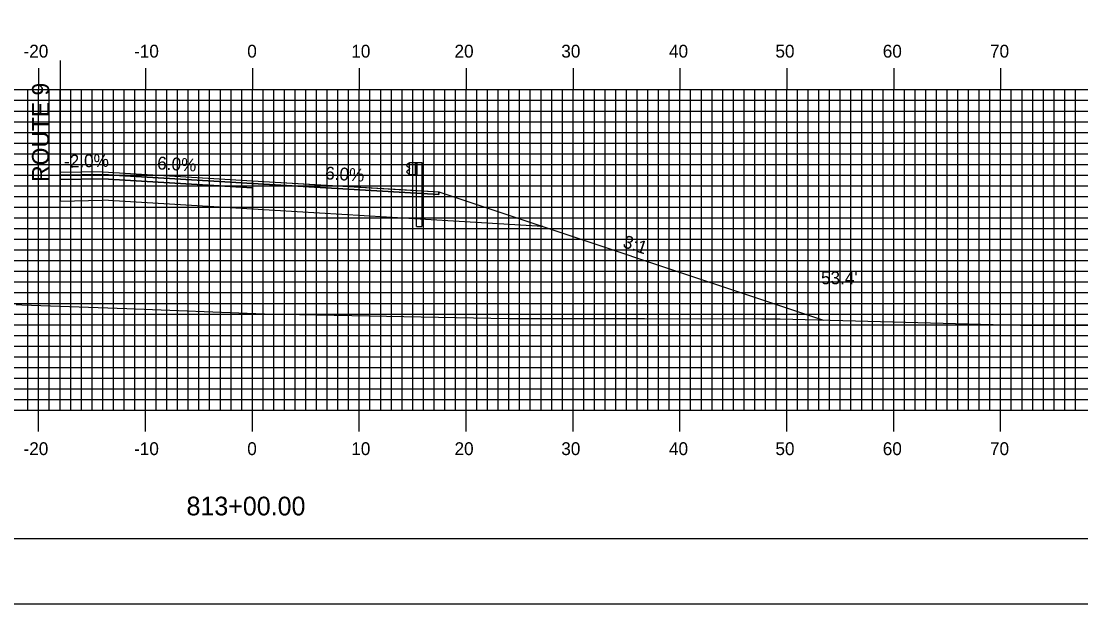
# Model space of a CAD drawing. Extents: x 2453 to 2796, y -1658 to -1438.
# Drawn here: x 2597.1 to 2696.2, y -1657.7 to -1603.2 of the extents above; entities that cross this region are included whole.
import ezdxf

# ---------------------------------------------------------------- set-up
doc = ezdxf.new("R2010")
doc.units = 0
for name, color, linetype in [('ANNOTATION', 7, 'Continuous'), ('BORDER', 7, 'Continuous'), ('D_Guardrail_Beam_Rt', 7, 'Continuous'), ('D_Roadway_Edge_Shoulder', 7, 'Continuous'), ('D_Roadway_Edge_TW', 7, 'Continuous'), ('D_Roadway_Pavement', 7, 'Continuous'), ('D_Roadway_SlopeLines', 7, 'Continuous'), ('D_Roadway_SubGrade', 7, 'Continuous'), ('D_Text_Standard', 7, 'Continuous'), ('H_V ANNOTATION', 7, 'Continuous'), ('MAJOR', 7, 'Continuous'), ('MINOR', 7, 'Continuous'), ('PLOT BOUNDARY', 7, 'Continuous'), ('S_Roadway_Centerline', 7, 'Continuous')]:
    doc.layers.add(name, color=color, linetype=linetype)

msp = doc.modelspace()

# ---------------------------------------------------------------- linework, layer by layer
at = {"layer": 'BORDER'}
msp.add_lwpolyline([(2469.1, -1651.604), (2789.1, -1651.604), (2789.1, -1441.604), (2469.1, -1441.604)], close=True, dxfattribs=at)
at = {"layer": 'D_Guardrail_Beam_Rt'}
for p, q in [((2633.307, -1616.511), (2633.164, -1616.611)), ((2633.164, -1616.754), (2633.359, -1616.891)), ((2633.397, -1616.49), (2633.323, -1616.505)), ((2633.397, -1616.407), (2634.085, -1616.407)), ((2633.397, -1617.573), (2633.397, -1616.407)), ((2633.918, -1616.407), (2633.918, -1617.573)), ((2634.022, -1616.407), (2634.022, -1617.573)), ((2634.085, -1616.407), (2634.555, -1616.407)), ((2634.085, -1616.407), (2634.085, -1617.573)), ((2634.555, -1616.407), (2634.555, -1622.407)), ((2633.359, -1617.089), (2633.164, -1617.226)), ((2633.164, -1617.369), (2633.307, -1617.469)), ((2633.323, -1617.475), (2633.397, -1617.49)), ((2633.393, -1616.955), (2633.393, -1617.025)), ((2634.085, -1617.573), (2633.397, -1617.573)), ((2634.064, -1622.407), (2634.064, -1617.573)), ((2634.064, -1622.407), (2634.555, -1622.407))]:
    msp.add_line(p, q, dxfattribs=at)
for centre, major_axis, start_param, end_param in [((2633.214, -1616.683), (-0.0877, 0), 5.323254, 7.243116), ((2633.331, -1616.545), (-0.0417, 0), 4.907132, 5.323254), ((2633.214, -1617.297), (-0.0877, 0), 5.323254, 7.243116), ((2633.331, -1617.435), (-0.0417, 0), 0.959931, 1.376053), ((2633.314, -1616.955), (0.0789, 0), 0, 0.959931), ((2633.314, -1617.025), (0.0789, 0), 5.323254, 6.283185)]:
    msp.add_ellipse(centre, major_axis=major_axis, ratio=0.995501, start_param=start_param, end_param=end_param, dxfattribs=at)
at = {"layer": 'D_Roadway_Edge_Shoulder'}
for points in [[(2604.7, -1617.284), (2600.7, -1617.361), (2600.7, -1617.611), (2604.7, -1617.534)], [(2604.7, -1617.284), (2600.7, -1617.361), (2600.7, -1617.611), (2604.7, -1617.534)], [(2618.7, -1618.124), (2633.126, -1618.99), (2633.126, -1618.99), (2636.126, -1619.17), (2636.126, -1619.42), (2618.7, -1618.374)], [(2618.7, -1618.124), (2636.126, -1619.17), (2636.126, -1619.42), (2618.7, -1618.374)], [(2618.7, -1618.124), (2633.126, -1618.99), (2633.126, -1618.99), (2636.126, -1619.17), (2636.126, -1619.42), (2618.7, -1618.374)]]:
    msp.add_lwpolyline(points, close=True, dxfattribs=at)
at = {"layer": 'D_Roadway_Edge_TW'}
msp.add_lwpolyline([(2604.7, -1617.284), (2618.7, -1618.124), (2618.7, -1618.374), (2604.7, -1617.534)], close=True, dxfattribs=at)
msp.add_lwpolyline([(2604.7, -1617.284), (2618.7, -1618.124), (2618.7, -1618.374), (2604.7, -1617.534)], close=True, dxfattribs=at)
msp.add_lwpolyline([(2604.7, -1617.284), (2618.7, -1618.124), (2618.7, -1618.374), (2604.7, -1617.534)], close=True, dxfattribs=at)
msp.add_lwpolyline([(2604.7, -1617.284), (2618.7, -1618.124), (2618.7, -1618.374), (2604.7, -1617.534)], close=True, dxfattribs=at)
at = {"layer": 'D_Roadway_Pavement'}
for points in [[(2604.7, -1617.534), (2600.7, -1617.611), (2600.7, -1618.028), (2604.7, -1617.951)], [(2604.7, -1617.534), (2600.7, -1617.611), (2600.7, -1618.028), (2604.7, -1617.951)], [(2604.7, -1617.534), (2618.7, -1618.374), (2618.7, -1618.791), (2604.7, -1617.951)], [(2604.7, -1617.534), (2618.7, -1618.374), (2618.7, -1618.791), (2604.7, -1617.951)], [(2604.7, -1617.534), (2618.7, -1618.374), (2618.7, -1618.791), (2604.7, -1617.951)], [(2604.7, -1617.534), (2618.7, -1618.374), (2618.7, -1618.791), (2604.7, -1617.951)]]:
    msp.add_lwpolyline(points, close=True, dxfattribs=at)
msp.add_lwpolyline([(2618.7, -1618.374), (2618.7, -1618.791)], dxfattribs=at)
msp.add_lwpolyline([(2618.7, -1618.374), (2618.7, -1618.791)], dxfattribs=at)
msp.add_lwpolyline([(2618.7, -1618.374), (2618.7, -1618.791)], dxfattribs=at)
msp.add_lwpolyline([(2618.7, -1618.374), (2618.7, -1618.791)], dxfattribs=at)
msp.add_lwpolyline([(2618.7, -1618.374), (2618.7, -1618.791)], dxfattribs=at)
msp.add_lwpolyline([(2618.7, -1618.374), (2618.7, -1618.791)], dxfattribs=at)
msp.add_lwpolyline([(2618.7, -1618.374), (2618.7, -1618.791)], dxfattribs=at)
msp.add_lwpolyline([(2618.7, -1618.374), (2618.7, -1618.791)], dxfattribs=at)
msp.add_lwpolyline([(2618.7, -1618.374), (2618.7, -1618.791)], dxfattribs=at)
msp.add_lwpolyline([(2618.7, -1618.374), (2618.7, -1618.791)], dxfattribs=at)
msp.add_lwpolyline([(2618.7, -1618.374), (2618.7, -1618.791)], dxfattribs=at)
msp.add_lwpolyline([(2618.7, -1618.374), (2618.7, -1618.791)], dxfattribs=at)
msp.add_lwpolyline([(2618.7, -1618.374), (2618.7, -1618.791)], dxfattribs=at)
msp.add_lwpolyline([(2618.7, -1618.374), (2618.7, -1618.791)], dxfattribs=at)
at = {"layer": 'D_Roadway_SlopeLines'}
msp.add_lwpolyline([(2636.126, -1619.17), (2672.138, -1631.174)], dxfattribs=at)
msp.add_lwpolyline([(2636.126, -1619.17), (2672.138, -1631.174)], dxfattribs=at)
at = {"layer": 'D_Roadway_SubGrade'}
msp.add_line((2600.7, -1606.888), (2600.7, -1620.028), dxfattribs=at)
for points in [[(2604.7, -1617.951), (2600.7, -1618.028), (2600.7, -1617.611), (2600.7, -1620.028), (2604.7, -1619.951)], [(2604.7, -1617.951), (2618.7, -1618.791), (2618.7, -1620.791), (2604.7, -1619.951)], [(2604.7, -1617.951), (2618.7, -1618.791), (2618.7, -1620.791), (2604.7, -1619.951)], [(2604.7, -1617.951), (2618.7, -1618.791), (2618.7, -1620.791), (2604.7, -1619.951)], [(2604.7, -1617.951), (2618.7, -1618.791), (2618.7, -1620.791), (2604.7, -1619.951)], [(2618.7, -1618.791), (2618.7, -1618.374), (2636.126, -1619.42), (2636.126, -1619.17), (2645.882, -1622.422), (2618.7, -1620.791)]]:
    msp.add_lwpolyline(points, close=True, dxfattribs=at)
at = {"layer": 'MAJOR'}
for p, q in [((2598.7, -1607.6), (2598.7, -1609.604)), ((2608.7, -1607.6), (2608.7, -1609.604)), ((2618.7, -1607.6), (2618.7, -1609.604)), ((2628.7, -1607.6), (2628.7, -1609.604)), ((2638.7, -1607.6), (2638.7, -1609.604)), ((2648.7, -1607.6), (2648.7, -1609.604)), ((2658.7, -1607.6), (2658.7, -1609.604)), ((2668.7, -1607.6), (2668.7, -1609.604)), ((2678.7, -1607.6), (2678.7, -1609.604)), ((2688.7, -1607.6), (2688.7, -1609.604)), ((2478.7, -1609.604), (2758.7, -1609.604)), ((2478.7, -1609.604), (2758.7, -1609.604)), ((2598.7, -1639.604), (2598.7, -1609.604)), ((2608.7, -1639.604), (2608.7, -1609.604)), ((2618.7, -1639.604), (2618.7, -1609.604)), ((2628.7, -1639.604), (2628.7, -1609.604)), ((2638.7, -1639.604), (2638.7, -1609.604)), ((2648.7, -1639.604), (2648.7, -1609.604)), ((2658.7, -1639.604), (2658.7, -1609.604)), ((2668.7, -1639.604), (2668.7, -1609.604)), ((2678.7, -1639.604), (2678.7, -1609.604)), ((2688.7, -1639.604), (2688.7, -1609.604)), ((2478.7, -1614.604), (2758.7, -1614.604)), ((2478.7, -1619.604), (2758.7, -1619.604)), ((2478.7, -1624.604), (2758.7, -1624.604)), ((2478.7, -1629.604), (2758.7, -1629.604)), ((2478.7, -1634.604), (2758.7, -1634.604)), ((2478.7, -1639.604), (2758.7, -1639.604)), ((2478.7, -1639.604), (2758.7, -1639.604)), ((2598.7, -1641.608), (2598.7, -1639.604)), ((2608.7, -1641.608), (2608.7, -1639.604)), ((2618.7, -1641.608), (2618.7, -1639.604)), ((2628.7, -1641.608), (2628.7, -1639.604)), ((2638.7, -1641.608), (2638.7, -1639.604)), ((2648.7, -1641.608), (2648.7, -1639.604)), ((2658.7, -1641.608), (2658.7, -1639.604)), ((2668.7, -1641.608), (2668.7, -1639.604)), ((2678.7, -1641.608), (2678.7, -1639.604)), ((2688.7, -1641.608), (2688.7, -1639.604))]:
    msp.add_line(p, q, dxfattribs=at)
at = {"layer": 'MINOR'}
for p, q in [((2597.7, -1639.604), (2597.7, -1609.604)), ((2599.7, -1639.604), (2599.7, -1609.604)), ((2600.7, -1639.604), (2600.7, -1609.604)), ((2601.7, -1639.604), (2601.7, -1609.604)), ((2602.7, -1639.604), (2602.7, -1609.604)), ((2603.7, -1639.604), (2603.7, -1609.604)), ((2604.7, -1639.604), (2604.7, -1609.604)), ((2605.7, -1639.604), (2605.7, -1609.604)), ((2606.7, -1639.604), (2606.7, -1609.604)), ((2607.7, -1639.604), (2607.7, -1609.604)), ((2609.7, -1639.604), (2609.7, -1609.604)), ((2610.7, -1639.604), (2610.7, -1609.604)), ((2611.7, -1639.604), (2611.7, -1609.604)), ((2612.7, -1639.604), (2612.7, -1609.604)), ((2613.7, -1639.604), (2613.7, -1609.604)), ((2614.7, -1639.604), (2614.7, -1609.604)), ((2615.7, -1639.604), (2615.7, -1609.604)), ((2616.7, -1639.604), (2616.7, -1609.604)), ((2617.7, -1639.604), (2617.7, -1609.604)), ((2619.7, -1639.604), (2619.7, -1609.604)), ((2620.7, -1639.604), (2620.7, -1609.604)), ((2621.7, -1639.604), (2621.7, -1609.604)), ((2622.7, -1639.604), (2622.7, -1609.604)), ((2623.7, -1639.604), (2623.7, -1609.604)), ((2624.7, -1639.604), (2624.7, -1609.604)), ((2625.7, -1639.604), (2625.7, -1609.604)), ((2626.7, -1639.604), (2626.7, -1609.604)), ((2627.7, -1639.604), (2627.7, -1609.604)), ((2629.7, -1639.604), (2629.7, -1609.604)), ((2630.7, -1639.604), (2630.7, -1609.604)), ((2631.7, -1639.604), (2631.7, -1609.604)), ((2632.7, -1639.604), (2632.7, -1609.604)), ((2633.7, -1639.604), (2633.7, -1609.604)), ((2634.7, -1639.604), (2634.7, -1609.604)), ((2635.7, -1639.604), (2635.7, -1609.604)), ((2636.7, -1639.604), (2636.7, -1609.604)), ((2637.7, -1639.604), (2637.7, -1609.604)), ((2639.7, -1639.604), (2639.7, -1609.604)), ((2640.7, -1639.604), (2640.7, -1609.604)), ((2641.7, -1639.604), (2641.7, -1609.604)), ((2642.7, -1639.604), (2642.7, -1609.604)), ((2643.7, -1639.604), (2643.7, -1609.604)), ((2644.7, -1639.604), (2644.7, -1609.604)), ((2645.7, -1639.604), (2645.7, -1609.604)), ((2646.7, -1639.604), (2646.7, -1609.604)), ((2647.7, -1639.604), (2647.7, -1609.604)), ((2649.7, -1639.604), (2649.7, -1609.604)), ((2650.7, -1639.604), (2650.7, -1609.604)), ((2651.7, -1639.604), (2651.7, -1609.604)), ((2652.7, -1639.604), (2652.7, -1609.604)), ((2653.7, -1639.604), (2653.7, -1609.604)), ((2654.7, -1639.604), (2654.7, -1609.604)), ((2655.7, -1639.604), (2655.7, -1609.604)), ((2656.7, -1639.604), (2656.7, -1609.604)), ((2657.7, -1639.604), (2657.7, -1609.604)), ((2659.7, -1639.604), (2659.7, -1609.604)), ((2660.7, -1639.604), (2660.7, -1609.604)), ((2661.7, -1639.604), (2661.7, -1609.604)), ((2662.7, -1639.604), (2662.7, -1609.604)), ((2663.7, -1639.604), (2663.7, -1609.604)), ((2664.7, -1639.604), (2664.7, -1609.604)), ((2665.7, -1639.604), (2665.7, -1609.604)), ((2666.7, -1639.604), (2666.7, -1609.604)), ((2667.7, -1639.604), (2667.7, -1609.604)), ((2669.7, -1639.604), (2669.7, -1609.604)), ((2670.7, -1639.604), (2670.7, -1609.604)), ((2671.7, -1639.604), (2671.7, -1609.604)), ((2672.7, -1639.604), (2672.7, -1609.604)), ((2673.7, -1639.604), (2673.7, -1609.604)), ((2674.7, -1639.604), (2674.7, -1609.604)), ((2675.7, -1639.604), (2675.7, -1609.604)), ((2676.7, -1639.604), (2676.7, -1609.604)), ((2677.7, -1639.604), (2677.7, -1609.604)), ((2679.7, -1639.604), (2679.7, -1609.604)), ((2680.7, -1639.604), (2680.7, -1609.604)), ((2681.7, -1639.604), (2681.7, -1609.604)), ((2682.7, -1639.604), (2682.7, -1609.604)), ((2683.7, -1639.604), (2683.7, -1609.604)), ((2684.7, -1639.604), (2684.7, -1609.604)), ((2685.7, -1639.604), (2685.7, -1609.604)), ((2686.7, -1639.604), (2686.7, -1609.604)), ((2687.7, -1639.604), (2687.7, -1609.604)), ((2689.7, -1639.604), (2689.7, -1609.604)), ((2690.7, -1639.604), (2690.7, -1609.604)), ((2691.7, -1639.604), (2691.7, -1609.604)), ((2692.7, -1639.604), (2692.7, -1609.604)), ((2693.7, -1639.604), (2693.7, -1609.604)), ((2694.7, -1639.604), (2694.7, -1609.604)), ((2695.7, -1639.604), (2695.7, -1609.604)), ((2478.7, -1610.604), (2758.7, -1610.604)), ((2478.7, -1611.604), (2758.7, -1611.604)), ((2478.7, -1612.604), (2758.7, -1612.604)), ((2478.7, -1613.604), (2758.7, -1613.604)), ((2478.7, -1615.604), (2758.7, -1615.604)), ((2478.7, -1616.604), (2758.7, -1616.604)), ((2478.7, -1617.604), (2758.7, -1617.604)), ((2478.7, -1618.604), (2758.7, -1618.604)), ((2478.7, -1620.604), (2758.7, -1620.604)), ((2478.7, -1621.604), (2758.7, -1621.604)), ((2478.7, -1622.604), (2758.7, -1622.604)), ((2478.7, -1623.604), (2758.7, -1623.604)), ((2478.7, -1625.604), (2758.7, -1625.604)), ((2478.7, -1626.604), (2758.7, -1626.604)), ((2478.7, -1627.604), (2758.7, -1627.604)), ((2478.7, -1628.604), (2758.7, -1628.604)), ((2478.7, -1630.604), (2758.7, -1630.604)), ((2478.7, -1631.604), (2758.7, -1631.604)), ((2478.7, -1632.604), (2758.7, -1632.604)), ((2478.7, -1633.604), (2758.7, -1633.604)), ((2478.7, -1635.604), (2758.7, -1635.604)), ((2478.7, -1636.604), (2758.7, -1636.604)), ((2478.7, -1637.604), (2758.7, -1637.604)), ((2478.7, -1638.604), (2758.7, -1638.604))]:
    msp.add_line(p, q, dxfattribs=at)
at = {"layer": 'PLOT BOUNDARY'}
msp.add_lwpolyline([(2452.913, -1657.723), (2792.913, -1657.723), (2792.913, -1437.723), (2452.913, -1437.723)], close=True, dxfattribs=at)
at = {"layer": 'S_Roadway_Centerline'}
msp.add_lwpolyline([(2596.6, -1629.72), (2597.115, -1629.733), (2606.942, -1630.073), (2619.817, -1630.578), (2621.493, -1630.627), (2642.625, -1631.034), (2644.607, -1631.029), (2655.367, -1631.012), (2666.349, -1631.052), (2667.2, -1631.043), (2668.062, -1631.067), (2687.998, -1631.59), (2689.213, -1631.603), (2690.555, -1631.633), (2701.945, -1631.691), (2712.495, -1631.684), (2714.017, -1631.663), (2735.799, -1631.817), (2736.867, -1631.828), (2758.391, -1632.069), (2758.7, -1632.076)], dxfattribs=at)

# ---------------------------------------------------------------- texts
at = {"layer": 'ANNOTATION'}
for s, height, rotation, p in [('ROUTE 9', 1.6, 90, (2599.68, -1618.237)), ('-2.0%', 1.2, 1.10002, (2601.088, -1616.906)), ('6.0%', 1.2, 356.56637, (2609.766, -1617.054)), ('6.0%', 1.2, 356.56636, (2625.48, -1617.996)), ('3:1', 1.2, 341.56503, (2653.272, -1624.323))]:
    msp.add_text(s, height=height, rotation=rotation, dxfattribs=at).set_placement(p)
at = {"layer": 'D_Text_Standard'}
msp.add_text("53.4'", height=1.2, dxfattribs=at).set_placement((2671.894, -1627.817))
at = {"layer": 'H_V ANNOTATION'}
for s, height, p in [('-20', 1.2, (2597.287, -1606.604)), ('-10', 1.2, (2607.63, -1606.604)), ('0', 1.2, (2618.218, -1606.604)), ('10', 1.2, (2627.95, -1606.604)), ('20', 1.2, (2637.608, -1606.604)), ('30', 1.2, (2647.597, -1606.604)), ('40', 1.2, (2657.672, -1606.604)), ('50', 1.2, (2667.629, -1606.604)), ('60', 1.2, (2677.672, -1606.604)), ('70', 1.2, (2687.704, -1606.604)), ('-20', 1.2, (2597.287, -1643.804)), ('-10', 1.2, (2607.63, -1643.804)), ('0', 1.2, (2618.218, -1643.804)), ('10', 1.2, (2627.95, -1643.804)), ('20', 1.2, (2637.608, -1643.804)), ('30', 1.2, (2647.597, -1643.804)), ('40', 1.2, (2657.672, -1643.804)), ('50', 1.2, (2667.629, -1643.804)), ('60', 1.2, (2677.672, -1643.804)), ('70', 1.2, (2687.704, -1643.804)), ('813+00.00', 1.75, (2612.536, -1649.448))]:
    msp.add_text(s, height=height, dxfattribs=at).set_placement(p)

doc.saveas('drawing.dxf')
